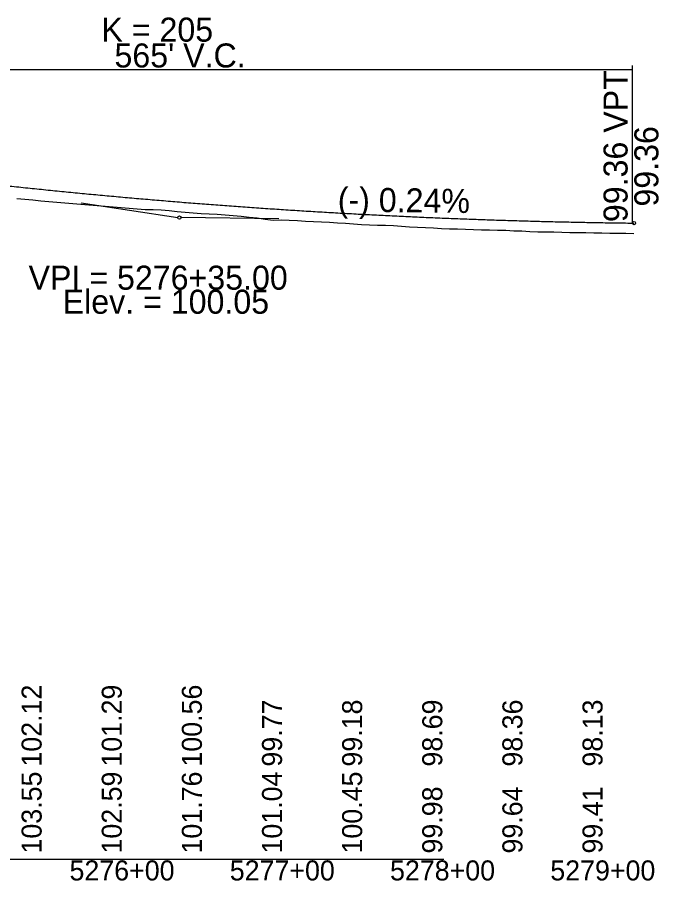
# Model space of a CAD drawing. Extents: x 2121671 to 2169879, y 557274 to 599957.
# Drawn here: x 2157102 to 2157502, y 579173 to 579712 of the extents above; entities that cross this region are included whole.
import ezdxf

# ---------------------------------------------------------------- set-up
doc = ezdxf.new("R2010")
doc.units = 0
for name, color, linetype in [('RD_DDB_GradeTX', 7, 'Continuous'), ('RD_DDB_Profile_EX', 7, 'Continuous'), ('RD_DDB_Profile_Lbl', 7, 'Continuous'), ('RD_DDB_Profile_PR', 7, 'Continuous'), ('RD_DDB_StaTX', 7, 'Continuous'), ('RD_DDB_StripGrade', 7, 'Continuous'), ('RD_DDB_VCLbl', 7, 'Continuous'), ('RD_GPK_Profile_Cell', 7, 'Continuous')]:
    doc.layers.add(name, color=color, linetype=linetype)

msp = doc.modelspace()

# ---------------------------------------------------------------- linework, layer by layer
at = {"layer": 'RD_DDB_GradeTX'}
for p, q in [((2157141.62, 579596.26), (2157201.95, 579587.21)), ((2157264.93, 579586.31), (2157203.93, 579587.05))]:
    msp.add_line(p, q, dxfattribs=at)
for centre in [(2157202.93, 579587.07), (2157486.53, 579583.63)]:
    msp.add_circle(centre, 1, dxfattribs=at)
at = {"layer": 'RD_DDB_Profile_EX'}
for points in [[(2157101.48, 579598.99), (2157106.48, 579598.51), (2157111.48, 579598.06), (2157116.48, 579597.54), (2157121.48, 579597.08), (2157126.48, 579596.62), (2157131.48, 579596.16), (2157136.48, 579595.75), (2157141.48, 579595.36), (2157146.48, 579595), (2157151.48, 579594.65), (2157156.48, 579594.2), (2157161.48, 579593.83), (2157166.48, 579593.4), (2157171.48, 579592.92), (2157176.48, 579592.42), (2157181.48, 579592.07), (2157186.48, 579592.1), (2157191.48, 579591.86), (2157196.48, 579591.4), (2157201.48, 579590.95), (2157206.48, 579590.5), (2157211.48, 579589.99), (2157216.48, 579589.7), (2157221.48, 579589.45)], [(2157221.48, 579589.45), (2157226.48, 579589.11), (2157231.48, 579588.68), (2157236.48, 579588.39), (2157241.48, 579587.88), (2157246.48, 579587.4), (2157251.48, 579586.96), (2157256.48, 579586.09), (2157261.48, 579585.55), (2157266.48, 579585.73), (2157271.48, 579585.51), (2157276.48, 579585.19), (2157281.48, 579584.88), (2157286.48, 579584.59), (2157291.48, 579584.34), (2157296.48, 579584.11), (2157301.48, 579583.86), (2157306.48, 579583.59), (2157311.48, 579583.16), (2157316.48, 579582.81), (2157321.48, 579582.57), (2157326.48, 579582.41), (2157331.48, 579582.23), (2157336.48, 579582.02), (2157341.48, 579581.7), (2157346.48, 579581.33), (2157351.48, 579581.09), (2157356.48, 579580.86), (2157361.48, 579580.61), (2157366.48, 579580.35), (2157371.48, 579580.09), (2157376.48, 579579.95), (2157381.48, 579579.85), (2157386.48, 579579.57), (2157391.48, 579579.47), (2157396.48, 579579.35), (2157401.48, 579579.23), (2157406.48, 579579.11), (2157411.48, 579578.84), (2157416.48, 579578.69), (2157421.48, 579578.47), (2157426.48, 579578.27), (2157431.48, 579578.27), (2157436.48, 579578.15), (2157441.48, 579577.99), (2157446.48, 579577.84), (2157451.48, 579577.73), (2157456.48, 579577.74), (2157461.48, 579577.62), (2157466.48, 579577.51), (2157471.48, 579577.4), (2157476.48, 579577.3), (2157481.48, 579577.26), (2157486.53, 579577.21)]]:
    msp.add_lwpolyline(points, dxfattribs=at)
at = {"layer": 'RD_DDB_Profile_PR'}
msp.add_line((2157485.43, 579583.64), (2157486.53, 579583.63), dxfattribs=at)
msp.add_spline([(2156920.43, 579629.44), (2156931.73, 579627.76), (2156943.03, 579626.11), (2156954.33, 579624.5), (2156965.63, 579622.91), (2156976.93, 579621.36), (2156988.23, 579619.83), (2156999.53, 579618.34), (2157010.83, 579616.88), (2157022.13, 579615.45), (2157033.43, 579614.05), (2157044.73, 579612.68), (2157056.03, 579611.34), (2157067.33, 579610.04), (2157078.63, 579608.76), (2157089.93, 579607.52), (2157101.23, 579606.31), (2157112.53, 579605.13), (2157123.83, 579603.98), (2157135.13, 579602.86), (2157146.43, 579601.77), (2157157.73, 579600.72), (2157169.03, 579599.69), (2157180.33, 579598.7), (2157191.63, 579597.74), (2157202.93, 579596.8), (2157214.23, 579595.9), (2157225.53, 579595.03), (2157236.83, 579594.2), (2157248.13, 579593.39), (2157259.43, 579592.61), (2157270.73, 579591.87), (2157282.03, 579591.16), (2157293.33, 579590.47), (2157304.63, 579589.82), (2157315.93, 579589.2), (2157327.23, 579588.61), (2157338.53, 579588.06), (2157349.83, 579587.53), (2157361.13, 579587.03), (2157372.43, 579586.57), (2157383.73, 579586.14), (2157395.03, 579585.73), (2157406.33, 579585.36), (2157417.63, 579585.02), (2157428.93, 579584.72), (2157440.23, 579584.44), (2157451.53, 579584.19), (2157462.83, 579583.98), (2157474.13, 579583.79), (2157485.43, 579583.64)], degree=3, dxfattribs=at)
at = {"layer": 'RD_DDB_VCLbl'}
for p, q in [((2157485.43, 579681.94), (2157485.43, 579583.64)), ((2156920.43, 579679.44), (2157485.43, 579679.44))]:
    msp.add_line(p, q, dxfattribs=at)
at = {"layer": 'RD_GPK_Profile_Cell'}
msp.add_line((2151067.93, 579186.83), (2157367.93, 579186.83), dxfattribs=at)

# ---------------------------------------------------------------- texts
at = {"layer": 'RD_DDB_GradeTX'}
msp.add_text('(-) 0.24%', height=15, rotation=359.3056, dxfattribs=at).set_placement((2157301.63, 579590.88))
at = {"layer": 'RD_DDB_Profile_Lbl'}
msp.add_text('99.36', height=15, rotation=90, dxfattribs=at).set_placement((2157501.77, 579593.92))
for s, p in [('VPI = 5276+35.00', (2157108.78, 579542.07)), ('Elev. = 100.05', (2157130.07, 579527.07))]:
    msp.add_text(s, height=15, dxfattribs=at).set_placement(p)
at = {"layer": 'RD_DDB_StaTX'}
for s, p in [('5276+00', (2157134.32, 579173.53)), ('5277+00', (2157234.32, 579173.53)), ('5278+00', (2157334.32, 579173.53)), ('5279+00', (2157434.32, 579173.53))]:
    msp.add_text(s, height=12.5, dxfattribs=at).set_placement(p)
at = {"layer": 'RD_DDB_StripGrade'}
for s, height, p in [('99.36 VPT', 15, (2157482.54, 579584.22)), ('102.12', 12.5, (2157116.93, 579244.56)), ('101.29', 12.5, (2157166.93, 579244.56)), ('100.56', 12.5, (2157216.93, 579244.56)), ('99.77', 12.5, (2157266.93, 579244.56)), ('99.18', 12.5, (2157316.93, 579244.56)), ('98.69', 12.5, (2157366.93, 579244.56)), ('98.36', 12.5, (2157416.93, 579244.56)), ('98.13', 12.5, (2157466.93, 579244.56)), ('103.55', 12.5, (2157116.93, 579190.33)), ('102.59', 12.5, (2157166.93, 579190.33)), ('101.76', 12.5, (2157216.93, 579190.33)), ('101.04', 12.5, (2157266.93, 579190.33)), ('100.45', 12.5, (2157316.93, 579190.33)), ('99.98', 12.5, (2157366.93, 579190.33)), ('99.64', 12.5, (2157416.93, 579190.33)), ('99.41', 12.5, (2157466.93, 579190.33))]:
    msp.add_text(s, height=height, rotation=90, dxfattribs=at).set_placement(p)
at = {"layer": 'RD_DDB_VCLbl'}
for s, p in [('K = 205', (2157154.24, 579696.8)), ("565' V.C.", (2157162.38, 579680.69))]:
    msp.add_text(s, height=15, dxfattribs=at).set_placement(p)

doc.saveas('drawing.dxf')
